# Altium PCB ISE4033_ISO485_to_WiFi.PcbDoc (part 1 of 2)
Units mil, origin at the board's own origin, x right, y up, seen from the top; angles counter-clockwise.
Board outline 4100 x 3450 mil, 4 copper layers (Top Layer, Signal Layer 1, Signal Layer 2, Bottom Layer), stack 52.6 mil thick; 125 components, 68 nets, 339 pads, 551 vias.
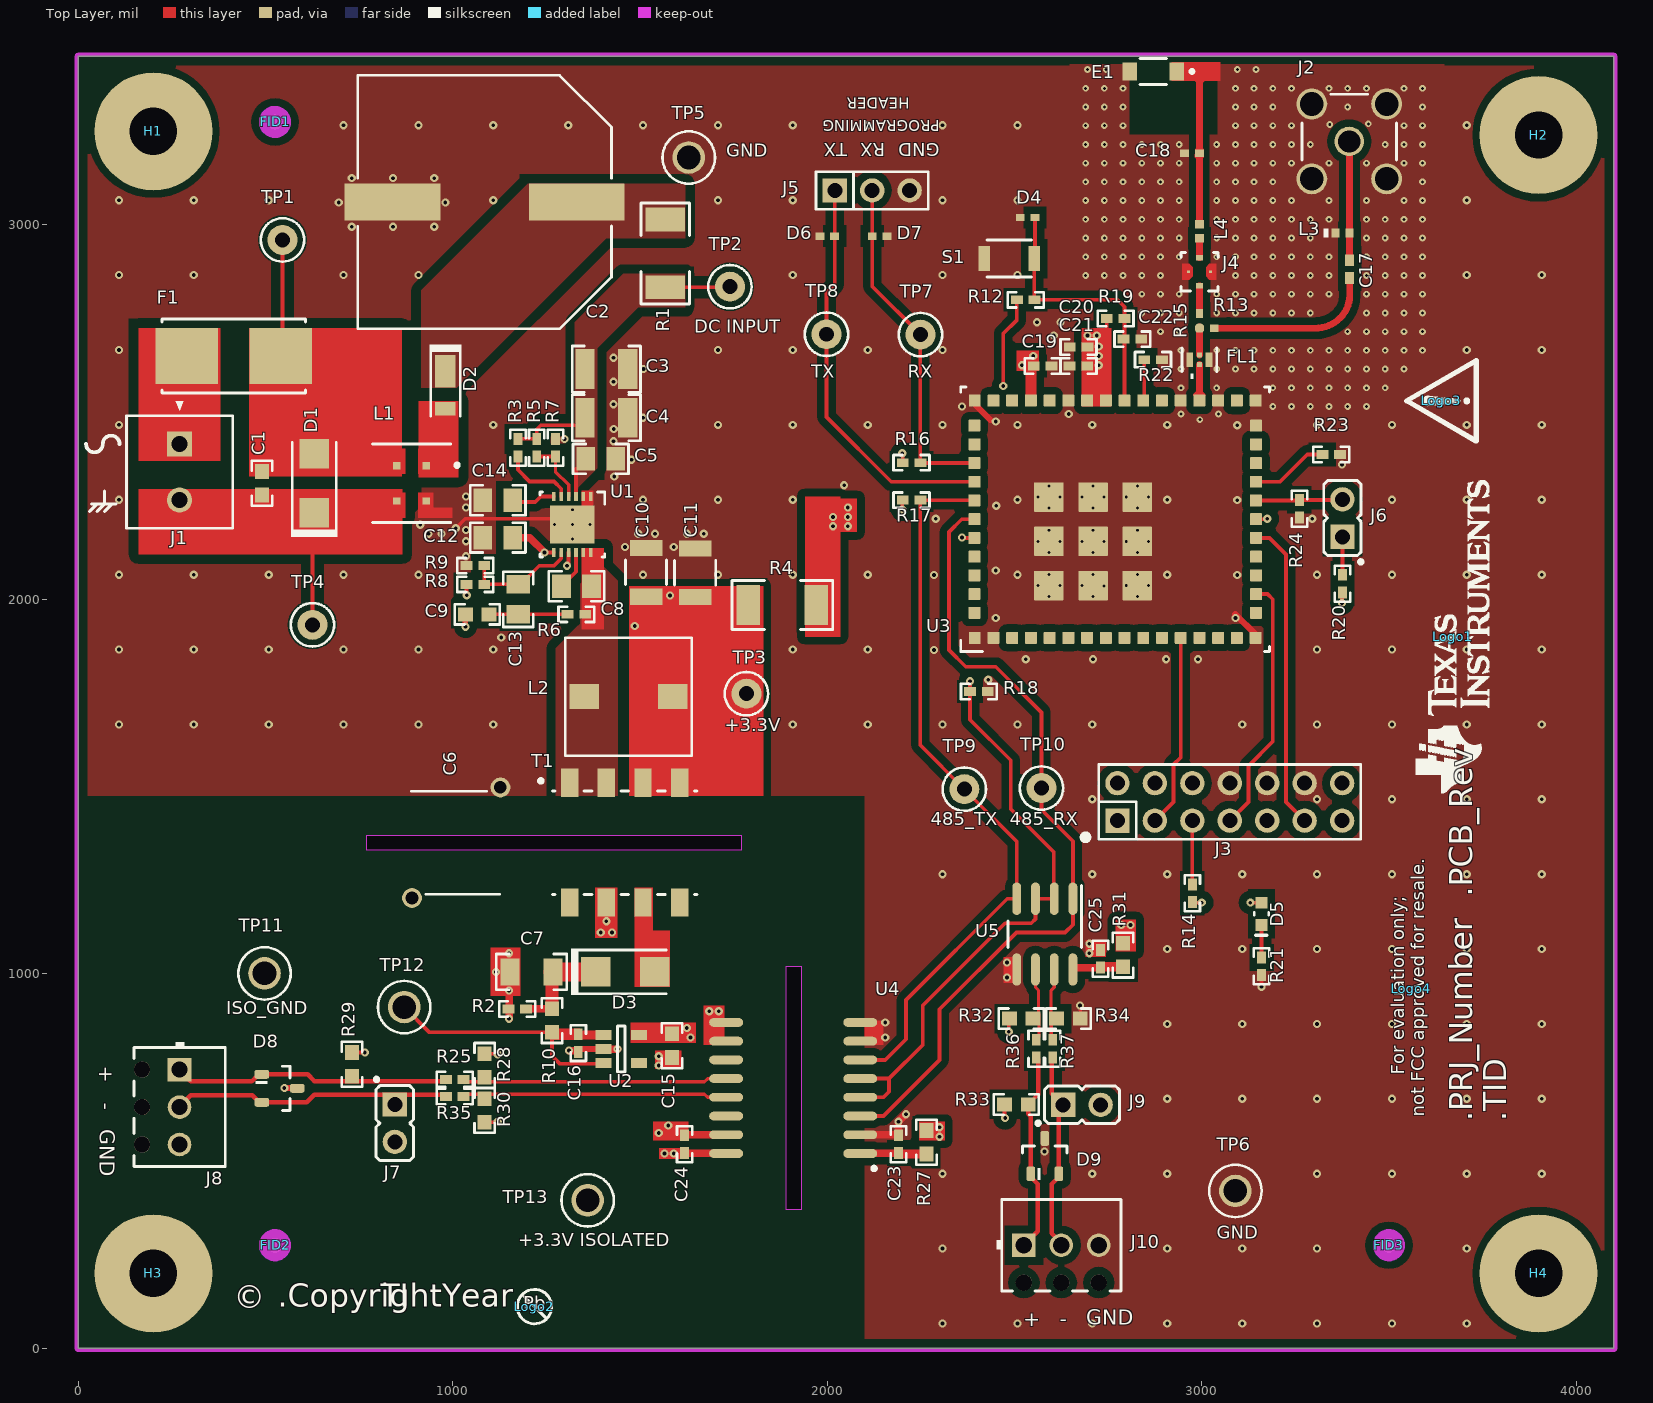
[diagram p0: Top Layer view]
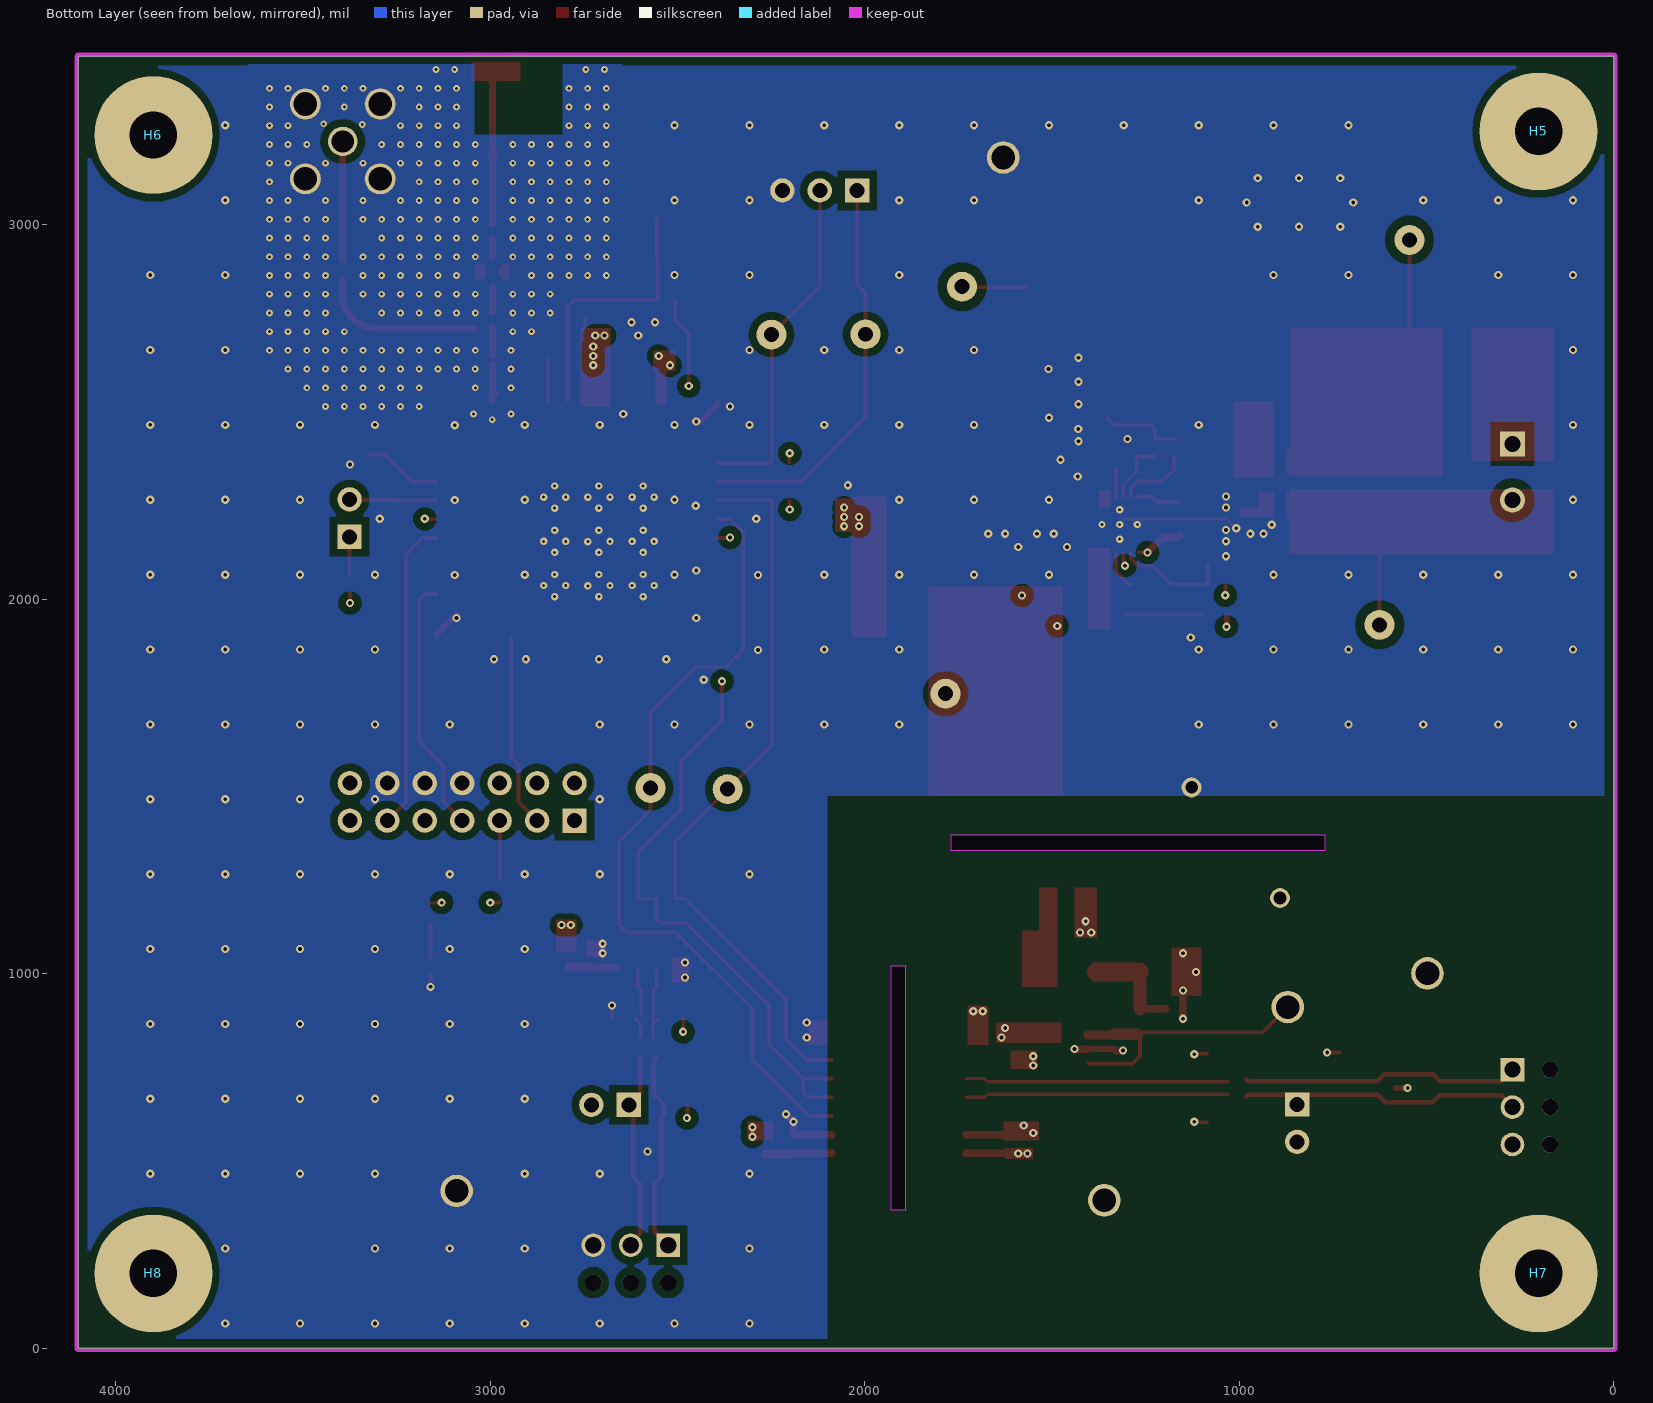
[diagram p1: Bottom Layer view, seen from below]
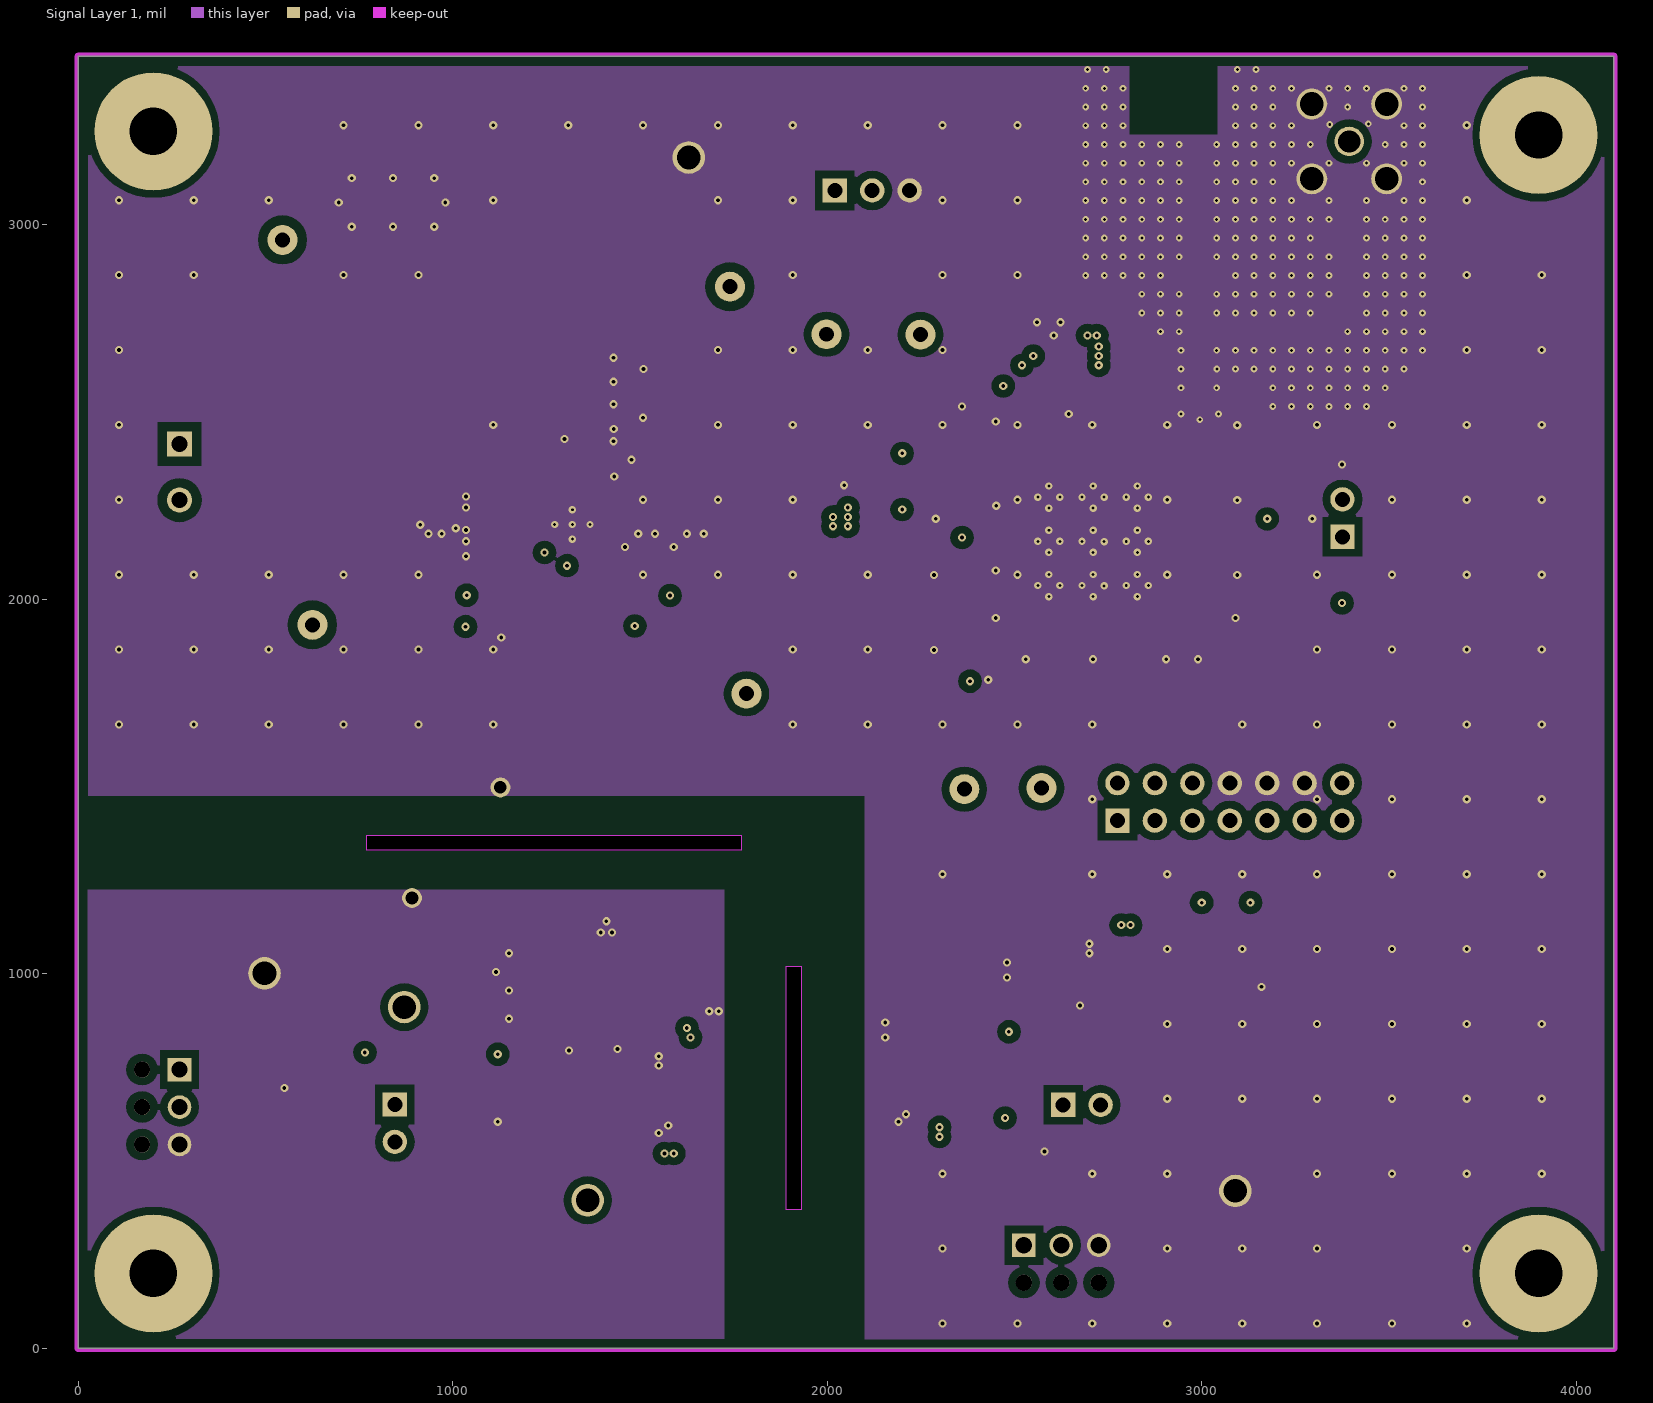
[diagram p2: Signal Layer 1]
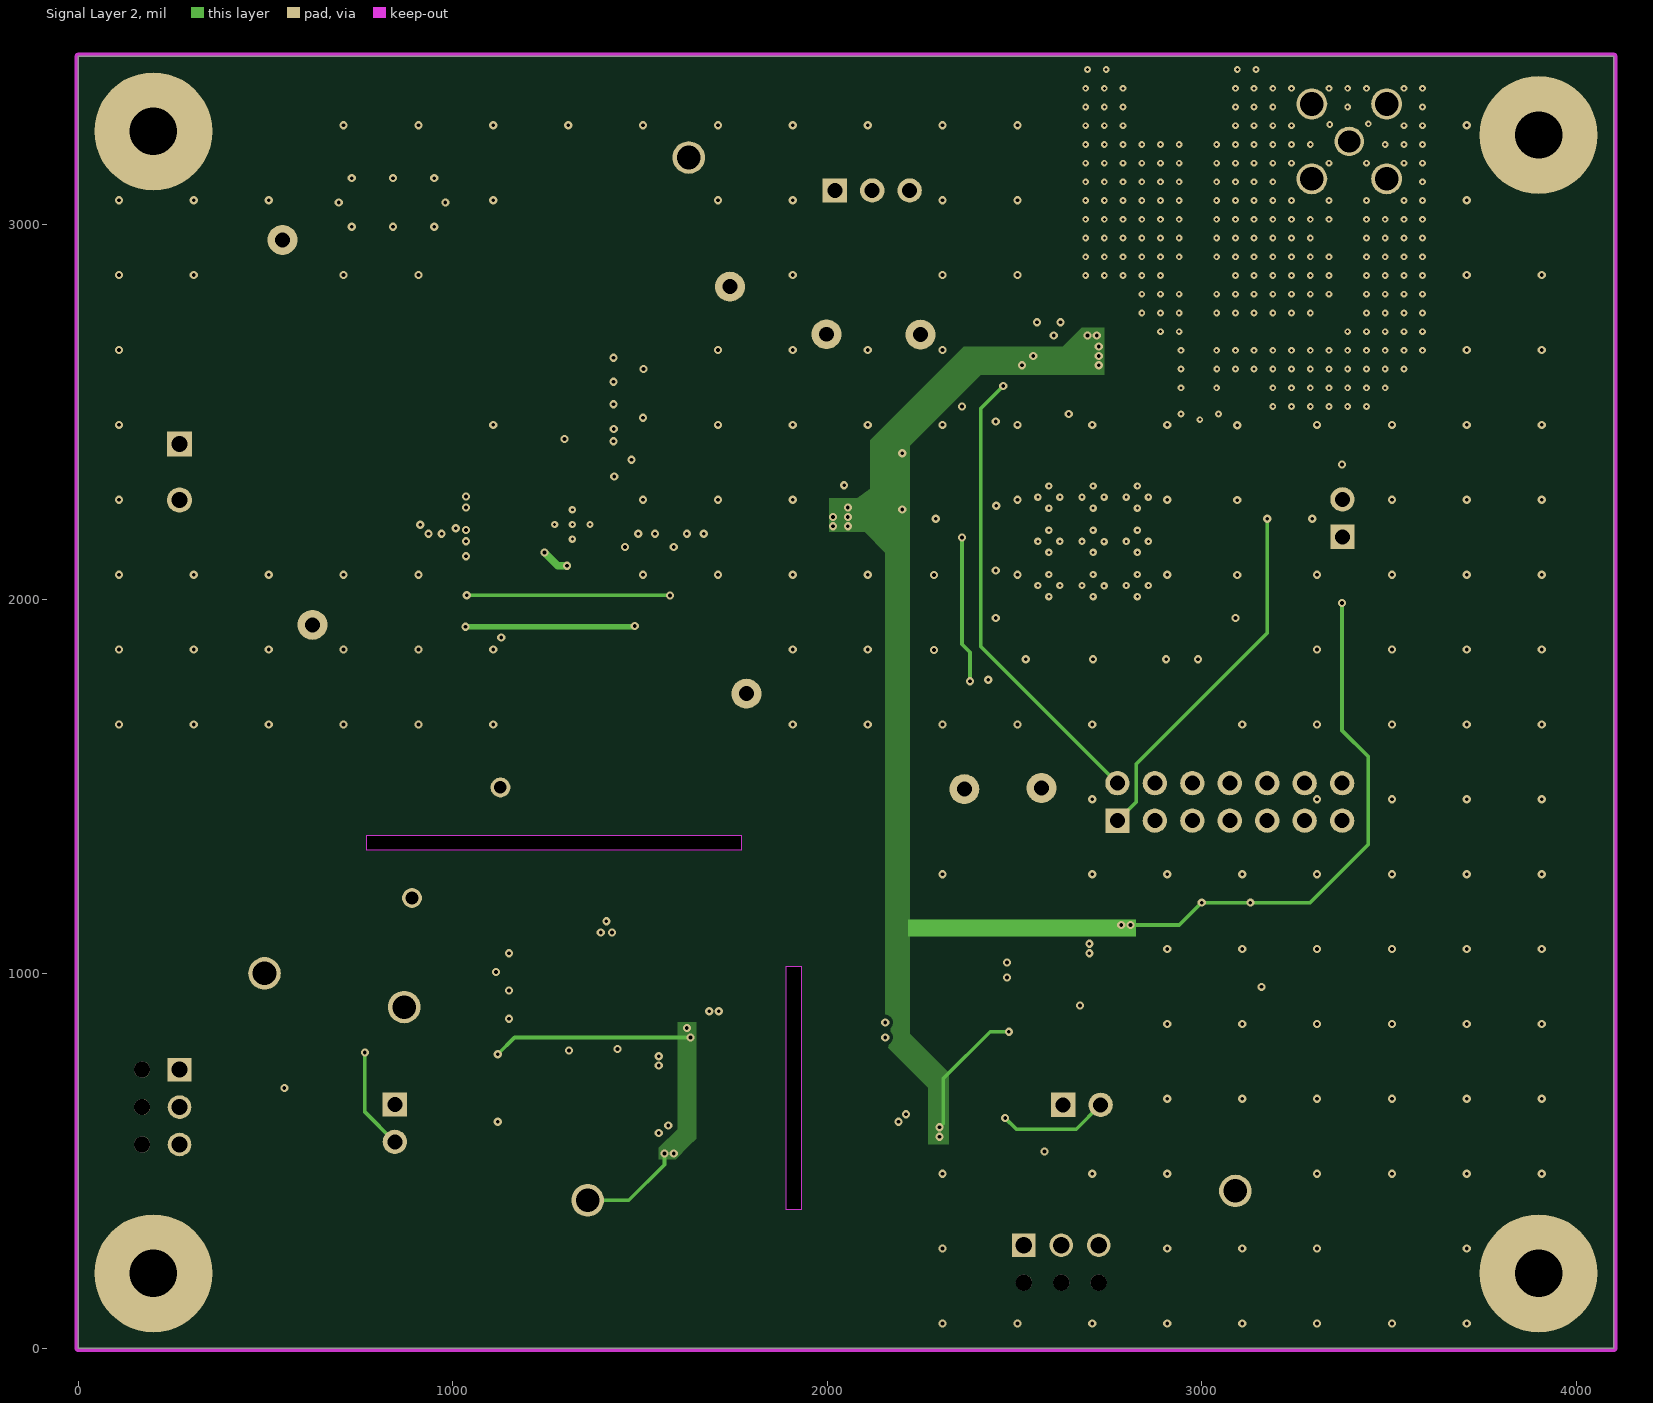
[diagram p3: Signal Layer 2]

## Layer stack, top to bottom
Top Solder: solder mask 0.4, Solder Resist, Dk 3.5
Top Layer: signal copper 1.4
Dielectric1: core 10, FR-4 High TG, Dk 4.2
Signal Layer 1: signal copper 1.4
Dielectric 2: prepreg 27, FR-4 High TG, Dk 4.2
Signal Layer 2: signal copper 1.4
Dielectric 3: core 10, FR-4 High TG, Dk 4.2
Bottom Layer: signal copper 1.4
Bottom Solder: solder mask 0.4, Solder Resist, Dk 3.5

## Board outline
0,0 4100,0 4100,3450 0,3450
cut-out: 1930,1020 1930,370 1890,370 1890,1020
cut-out: 770,1370 1770,1370 1770,1330 770,1330

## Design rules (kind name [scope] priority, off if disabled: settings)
AcuteAngle [All] p1: minimum=4.50000000000000E+0001 checktracksonly=FALSE
AssemblyTestPointUsage [All] p1: valid=2
Clearance "Clearance_special nets" [innet('IN1') or  innet('IN2') or    innet('IN1_F') or    innet('IN1_FL') or    innet('VIN_FLT') or    innet('PS_VIN') or    innet('BST') or    innet('SW') vs inpoly] p1: gap=25
Clearance "Clearance_GND poly" [(innet('GND') or innet('ISO_GND')) and inpoly] p2: gap=20
Clearance Clearance_Keepouts [((IsTrack Or IsArc) And Not InPoly) And IsFree and IsKeepOut vs ((IsTrack Or IsArc) And Not InPoly) And IsFree and IsKeepOut] p3: gap=0
Clearance Clearance_BoardEdge_MountingHoles [OnCopper and InComponentClass('Mounting Holes') vs IsKeepOut] p4: gap=40
Clearance Clearance_BoardEdge_Poly [OnCopper and InPoly vs IsKeepOut] p5: gap=25
Clearance Clearance_BoardEdge [OnCopper and Not InComponentClass('Logo') and not InComponentClass('FiducialMark') and not InRegion(1000,500,4000,800) and Not IsKeepout vs IsKeepOut] p6: gap=15
Clearance Clearance_Poly [InPolygon] p7: gap=10
Clearance [All] p8: gap=7.6
ComponentClearance ComponentClearance_1 [InComponent('R13') vs InComponent('R15')] p1: gap=0 collisioncheckmode=3 verticalgap=0 showdistances=FALSE
ComponentClearance ComponentClearance_MountingHoles_FiducialMarks [InComponentClass('Mounting Holes') vs InComponentClass('FiducialMark')] p2: gap=50 collisioncheckmode=3 verticalgap=10 showdistances=FALSE
ComponentClearance ComponentClearance_Shunt [InComponentClass('Header') vs InComponentClass('Shunt')] p3: gap=0 collisioncheckmode=3 verticalgap=0 showdistances=FALSE
ComponentClearance ComponentClearance_Logo [InComponentClass('Logo')] p4: gap=50 collisioncheckmode=3 verticalgap=10 showdistances=FALSE
ComponentClearance ComponentClearance_ScrewToNut [(HasFootprint('NY PMS 440 0025 PH')) vs (HasFootprint('Keystone_1902C'))] p5: gap=5 collisioncheckmode=3 verticalgap=10 showdistances=FALSE
ComponentClearance ComponentClearance_MountingHoles [InComponentClass('Mounting Holes')] p6: gap=100 collisioncheckmode=3 verticalgap=100000 showdistances=FALSE
ComponentClearance ComponentClearance_SmallPassives [HasFootprint('0201*') or HasFootprint('0402*') or HasFootprint('0508') or HasFootprint('0603*') or HasFootprint('0612') or HasFootprint('0805*') or HasFootprint('0815*') or HasFootprint('0830*') or HasFootprint('1206*') or HasFootprint('1210*') or HasFootprint('1808*') or HasFootprint('1812*') or HasFootprint('1825*') or HasFootprint('2010*') or HasFootprint('2220*') or HasFootprint('2225*') or HasFootprint('2512*') or HasFootprint('2728*') or HasFootprint('3518*') vs HasFootprint('0201*') or HasFootprint('0402*') or HasFootprint('0508') or HasFootprint('0603*') or HasFootprint('0612') or HasFootprint('0805*') or HasFootprint('0815*') or HasFootprint('0830*') or HasFootprint('1206*') or HasFootprint('1210*') or HasFootprint('1808*') or HasFootprint('1812*') or HasFootprint('1825*') or HasFootprint('2010*') or HasFootprint('2220*') or HasFootprint('2225*') or HasFootprint('2512*') or HasFootprint('2728*') or HasFootprint('3518*')] p7: gap=20 collisioncheckmode=3 verticalgap=10 showdistances=FALSE
ComponentClearance ComponentClearance_THtoSMT [IsThruComponent vs IsSMTComponent] p8: gap=25 collisioncheckmode=3 verticalgap=30 showdistances=FALSE
ComponentClearance ComponentClearance_THtoTH [IsThruComponent vs IsThruComponent] p9: gap=100 collisioncheckmode=3 verticalgap=30 showdistances=FALSE
ComponentClearance [All] p10: gap=40 collisioncheckmode=3 verticalgap=10 showdistances=FALSE
DiffPairsRouting DiffPairsRouting-140 [InDifferentialPair('ISO485') or  InDifferentialPair('RS485')] p1: maxlimit=70 minlimit=25 mostfreqgap=25 toplayer_minwidth=8.5 toplayer_maxwidth=8.5 toplayer_prefwidth=8.5 midlayer1_minwidth=8.5 midlayer1_maxwidth=8.5 midlayer1_prefwidth=8.5 midlayer2_minwidth=8.5 midlayer2_maxwidth=8.5 midlayer2_prefwidth=8.5 bottomlayer_minwidth=8.5 bottomlayer_maxwidth=8.5 bottomlayer_prefwidth=8.5 maxuncoupledlength=500
DiffPairsRouting DiffPairsRouting-120 [InDifferentialPair('ISO485_OUT') or  InDifferentialPair('RS485_OUT')] p2: maxlimit=70 minlimit=25 mostfreqgap=25 toplayer_minwidth=12 toplayer_maxwidth=12 toplayer_prefwidth=12 midlayer1_minwidth=12 midlayer1_maxwidth=12 midlayer1_prefwidth=12 midlayer2_minwidth=12 midlayer2_maxwidth=12 midlayer2_prefwidth=12 bottomlayer_minwidth=12 bottomlayer_maxwidth=12 bottomlayer_prefwidth=12 maxuncoupledlength=1000
FabricationTestPointUsage TestPointUsage [All] p1: valid=2 allowmultiple=FALSE
FabricationTestpoint Testpoint [All] p1: side=3 testpointundercomponent=TRUE minsize=40 maxsize=100 preferedsize=60 minholesize=0 maxholesize=40 preferedholesize=32 testpointgrid=1 allowsidetop=TRUE allowsidebottom=TRUE usegrid=TRUE gridtolerance=0.01
FanoutControl Fanout_LCC [IsLCC] p1: bgadir=Out bgaviamode=Centered fanoutstyle=Auto fanoutdirection=Alternating viagrid=1 // Fanout_LCC (Default Rule)
FanoutControl Fanout_BGA [IsBGA] p2: bgadir=Out bgaviamode=Centered fanoutstyle=Auto fanoutdirection=Alternating viagrid=1 // Fanout_BGA (Default Rule)
FanoutControl Fanout_Default [All] p4: bgadir=Out bgaviamode=Centered fanoutstyle=Auto fanoutdirection=Alternating viagrid=1 // Fanout_Default (Default Rule)
FanoutControl Fanout_Small [(CompPinCount < 5)] p5: bgadir=Out bgaviamode=Centered fanoutstyle=Auto fanoutdirection=OutThenIn viagrid=1 // Fanout_Small (Default Rule)
HoleSize [All] p1: absolutevalues=TRUE maxlimit=251 minlimit=7.8 maxpercent=80.000 minpercent=20.000
MinimumAnnularRing MinimumAnnularRing_ThermalPadVias [IsVia and InAnyComponent] p1: minimumring=5.91
MinimumAnnularRing [All] p2: minimumring=5
MinimumSolderMaskSliver MinimumSolderMaskSliver_Logo [InComponentClass('Logo') vs InComponentClass('Logo')] p1: minsoldermaskwidth=0.7
MinimumSolderMaskSliver [All] p2: minsoldermaskwidth=3.94
PlaneConnect [All] p1: planeconnectstyle=Relief reliefexpansion=10 reliefentries=4 reliefconductorwidth=10 reliefairgap=10
PolygonConnect [All] p1: connectstyle=Direct reliefconductorwidth=10 reliefentries=4 polygonreliefangle="90 Angle" airgapwidth=10
RoutingVias ThermalPadVias [IsVia and InAnyComponent] p1: holewidth=7.87 width=19.68 viastyle="Through Hole" minholewidth=7.87 minwidth=19.68 maxholewidth=12.99 maxwidth=23.62
RoutingVias [All] p2: holewidth=10 width=22 viastyle="Through Hole" minholewidth=7.87 minwidth=18 maxholewidth=40 maxwidth=65
SilkToBoardRegionClearance [Not ((IsComment or IsDesignator) And (Hide <> 'False')) and not InRegion(1000,500,4000,800)] p1:
SilkToSilkClearance SilkToSilkClearance_Pb-FreeLogo [(HasFootprint('Pb-Free_Overlay_Medium') OR HasFootprint('Pb-Free_Overlay_Small')) vs (HasFootprint('Pb-Free_Overlay_Medium') OR HasFootprint('Pb-Free_Overlay_Small'))] p1: silktosilkclearance=0
SilkToSilkClearance [All] p2: silktosilkclearance=3
SilkToSolderMaskClearance "Silk to Solder Mask Opening" [All] p1: minsilkscreentomaskgap=1 clearancetoexposedcopper=FALSE
SolderMaskExpansion [All] p1: expansion=1.97
UnpouredPolygon [All] p1: allowunpoured=FALSE
Width Width_50OHM [InNetClass('50 OHM')] p1: maxlimit=20 minlimit=18 preferedwidth=18
Width [All] p2: maxlimit=100 minlimit=8 preferedwidth=10 checkconnectedcopper=TRUE
14 further rules are at their usual default settings.

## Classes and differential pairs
component class ISE4037_RS485_to_WiFi_Sheet4: C23 C24 C25 D8 D9 J7 J8 J9 J10 R25 R27 R28 R29 R30 R31 R32 R33 R34 R35 R36 R37 SH-J7 SH-J9 SH-J10 SH-J11 U4 U5
component class AssemblyNote: ZZ1 ZZ2 ZZ3 ZZ4
component class FiducialMark: FID1 FID2 FID3
component class ISE4037_RS485_to_WiFi_Sheet5: FID1 FID2 FID3 H1 H2 H3 H4 H5 H6 H7 H8 Logo1 Logo2 Logo3 Logo4 ZZ1 ZZ2 ZZ3 ZZ4
component class Logo: Logo1
component class "Mounting Holes": H1 H2 H3 H4
component class Header: J3 J5 J6 J7 J9
component class ISE4037_RS485_to_WiFi_Sheet2: C1 C2 C3 C4 C5 C6 C7 C8 C9 C10 C11 C12 C13 C14 C15 C16 D1 D2 D3 D5 F1 J1 L1 L2 R1 R2 R3 R4 R5 R6 R7 R8 R9 R10 R21 T1 TP1 TP2 TP3 TP4 TP5 TP6 TP11 TP12 TP13 U1 U2
component class ISE4037_RS485_to_WiFi_Sheet3: C17 C18 C19 C20 C21 C22 D4 D6 D7 E1 FL1 J2 J3 J4 J5 J6 L3 L4 R12 R13 R14 R15 R16 R17 R18 R19 R20 R22 R23 R24 S1 TP7 TP8 TP9 TP10 U3
net class "50 OHM": ANT_LEG CC_RF_OUT J4-2 RF_FL_O SMA_LEG SMA_OUT
differential pair RS485: +RS485_P -RS485_N
differential pair RS485_OUT: +RS485_OUT_P -RS485_OUT_N
differential pair ISO485: +ISO485_P -ISO485_N
differential pair ISO485_OUT: +ISO485_OUT_P -ISO485_OUT_N

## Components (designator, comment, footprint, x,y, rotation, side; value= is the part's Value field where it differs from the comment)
C1 "06031C102KAT2A" 0603 490,2310 r270 top
C2 "EEV-FK1K331M" SM_RADIAL_J16 1085,3061 r180 top
C3 "C1210C225K1RACTU" 1210 1410,2615 r0 top
C4 "C1210C225K1RACTU" 1210 1410,2485 r0 top
C5 "C0805C104K1RACTU" 0805_HV 1395,2375 r0 top
C6 "DEBE33F102ZC3B" CAPRD750W60D700H1000 1009,1350 r90 top
C7 "C3216X7R1C475K" 1206 1210,1005 r180 top
C8 "08051C223KAT2A" 0805_HV 1330,2035 r180 top
C9 "06031C472KAT2A" 0603 1065,1960 r0 top
C10 "C1210C107M8PACTU" 1210_280 1516,2072 r90 top
C11 "C1210C107M8PACTU" 1210_280 1647,2071 r90 top
C12 "C0805C104K1RACTU" 0805_HV 1120,2165 r180 top
C13 "C0805C104K1RACTU" 0805_HV 1175,2000 r90 top
C14 "C0805C823K1RACTU" 0805_HV 1120,2265 r180 top
C15 "GRM188R71A105KA61D" 0603 1585,808 r270 top
C16 "GRM155R71A104KA01D" 0402 1335,815 r270 top
C17 "GRM1555C1H100JA01D" 0402 3395,2882 r270 top
C18 "GRM1555C1H1R0BA01D" 0402L#1 2974,3191 r180 top
C19 "GRM155R60J475ME87D" 0402 2575,2623 r0 top
C20 "GRM155R71A104KA01D" 0402 2671,2674 r180 top
C21 "GRM155R60J475ME87D" 0402 2670.92,2623.03 r180 top
C22 "GRM155R71A104KA01D" 0402 2815,2695 r0 top
C23 "GRM155R71A104KA01D" 0402 2190,545 r270 top
C24 "GRM155R71A104KA01D" 0402 1619,545 r270 top
C25 "GRM155R71A104KA01D" 0402 2730,1040 r270 top
D1 "SMAJ51CA" SMA 630,2310 r90 top
D2 "DFLS1200-7" powerDI123 980,2559 r270 top
D3 "CD214A-B1100LF" SMA 1460,1005 r0 top
D4 "TPD1E10B06DPYR" DPY0002A 2535,3020 r180 top
D5 "LG L29K-G2J1-24-Z" "LG L29K_GREEN" 3160,1160 r270 top
D6 "TPD1E10B06DPYR" DPY0002A 2000,2970 r180 top
D7 "TPD1E10B06DPYR" DPY0002A 2140,2970 r0 top
D8 "SM712.TCT" SOT-23 537,694 r0 top
D9 "SM712.TCT" SOT-23 2581,513 r90 top
E1 "AH316M245001-T" TAYO_AH316M 2870.5,3410 r180 top locked
F1 "0154002.DRT" FUSE_154 415,2650 r180 top
FID1 "Fiducial" Fiducial10-20 525,3275 r0 top
FID2 "Fiducial" Fiducial10-20 525,275 r0 top
FID3 "Fiducial" Fiducial10-20 3500,275 r0 top
FL1 "DEA202450BT-1294C1-H" TDK_DEA202450BT-1294C1-H 2994,2640 r180 top
H1 "NY PMS 440 0025 PH" "NY PMS 440 0025 PH" 200,3250 r0 top locked
H2 "NY PMS 440 0025 PH" "NY PMS 440 0025 PH" 3900,3240 r0 top locked
H3 "NY PMS 440 0025 PH" "NY PMS 440 0025 PH" 200,200 r0 top locked
H4 "NY PMS 440 0025 PH" "NY PMS 440 0025 PH" 3900,200 r0 top locked
H5 "1902C" Keystone_1902C 200,3250 r180 bottom locked
H6 "1902C" Keystone_1902C 3900,3240 r180 bottom locked
H7 "1902C" Keystone_1902C 200,200 r180 bottom locked
H8 "1902C" Keystone_1902C 3900,200 r180 bottom locked
J1 "1727010" PhoenixConact_1727010 270,2340 r270 top
J2 "5-1814832-1" TE_5-1814832-1 3394,3223 r90 top
J3 "PEC07DAAN" CONN_PEC07DAAN 3075,1459 r0 top
J4 "MM8030-2610RJ3" MuRata_MM8030-2610 2994,2875 r90 top
J5 "PBC03SAAN" PBC03SAAN 2120,3092 r0 top
J6 "PBC02SAAN" Sullins_PBC02SAAN 3375.92,2217.03 r180 top
J7 "PBC02SAAN" Sullins_PBC02SAAN 845,601 r0 top
J8 "1725669" Phoenix_1725669 270,644 r270 top
J9 "PBC02SAAN" Sullins_PBC02SAAN 2680,650 r90 top
J10 "1725669" Phoenix_1725669 2625,275 r0 top
L1 "DLW5BTM102TQ2K" DLW5BT_TQ2 890,2310 r270 top
L2 "7447789147" WE-PD-S 1469,1740 r0 top
L3 "LQG15HS3N6S02D" IND_LQG15H 3376,2978 r0 top
L4 "LQP15MN3N6B02D" LQP_0402 2994,2983 r90 top
Logo1 "Texas Instruments" TI_Stacked_Overlay_Small 3670,1900 r90 top
Logo2 "Pb-Free Symbol" Pb-Free_Overlay_Small 1218,111 r0 top
Logo3 "CAUTION.  READ USER GUIDE BEFORE USE" IEC_Caution_Small 3640,2530 r90 top
Logo4 "FCC disclaimer" FCC_disclaimer_stacked 3560,960 r90 top
R1 "CRCW20100000Z0EF" 2010 1567,2924 r270 top
R2 "CRCW04022K00FKED" 0402 1172,906 r0 top
R3 "CRCW0402110KFKED" 0402 1174,2405 r270 top
R4 "CRCW20100000Z0EF" 2010 1880,1985 r0 top
R5 "CRCW0402127KFKED" 0402 1224,2405 r90 top
R6 "CRCW0402100KFKED" 0402 1330,1960 r180 top
R7 "CRCW040217K8FKED" 0402 1274,2405 r270 top
R8 "CRCW04021K96FKED" 0402 1060,2040 r180 top
R9 "CRCW04023K01FKED" 0402 1060,2090 r0 top
R10 "CRCW06030000Z0EA" 0603 1265,875 r270 top
R12 "CRCW04020000Z0ED" 0402 2530,2800 r180 top
R13 "CRCW04020000Z0ED" 0402L#2 3014,2724 r0 top
R14 "CRCW04020000Z0ED" 0402 2975,1215 r270 top
R15 "CRCW04020000Z0ED" 0402L#3 2994,2744 r270 top
R16 "CRCW0402100KFKED" 0402 2225,2365 r180 top
R17 "CRCW0402100KFKED" 0402 2225,2265 r180 top
R18 "CRCW04022K67FKED" 0402 2405,1754 r180 top
R19 "CRCW0402100KFKED" 0402 2770,2750 r180 top
R20 "CRCW0402270RJNED" 0402 3375.92,2042.03 r270 top
R21 "CRCW0402402RFKED" 0402 3160,1020 r90 top
R22 "CRCW0402100KFKED" 0402 2870,2640 r180 top
R23 "CRCW0402100KFKED" 0402 3345.92,2387.03 r180 top
R24 "CRCW04022K67FKED" 0402 3260.92,2242.03 r90 top
R25 "CRCW040210R0FKED" 0402 1005,718 r180 top
R27 "CRCW06030000Z0EA" 0603 2265,550 r90 top
R28 "CRCW0603348RFKEA" 0603 1085,755 r90 top
R29 "RC0603FR-07120RL" 0603 731,758 r90 top
R30 "CRCW0603348RFKEA" 0603 1085,635 r90 top
R31 "CRCW06030000Z0EA" 0603 2790,1050 r90 top
R32 "CRCW0603348RFKEA" 0603 2518,880 r180 top
R33 "RC0603FR-07120RL" 0603 2505,651 r180 top
R34 "CRCW0603348RFKEA" 0603 2644,880 r180 top
R35 "CRCW040210R0FKED" 0402 1005,672 r180 top
R36 "CRCW040210R0FKED" 0402 2558,800 r270 top
R37 "CRCW040210R0FKED" 0402 2602,800 r270 top
S1 "B3U-1000P" SW_B3U-1000P 2485.92,2910.03 r180 top
T1 "750315547" Wurth_750315547_48 1459,1350 r0 top
TP1 "5002" Keystone5002 545,2960 r0 top
TP2 "5000" Keystone5000 1740,2835 r0 top
TP3 "5000" Keystone5000 1784,1748 r0 top
TP4 "5002" Keystone5002 625,1932 r0 top
TP5 "5128" Keystone5128 1630,3180 r0 top
TP6 "5128" Keystone5128 3090,420 r0 top
TP7 "5003" Keystone5003 2249,2707 r0 top
TP8 "5004" Keystone5004 1998,2708 r0 top
TP9 "5003" Keystone5003 2366,1493 r0 top
TP10 "5004" Keystone5004 2572,1496 r0 top
TP11 "5126" Keystone5126 497,1001 r0 top
TP12 "5129" Keystone5129 870,911 r0 top
TP13 "5125" Keystone5125 1360,395 r0 top
U1 "LM5160DNTR" DNT0012B 1319,2200 r270 top
U2 "TLV71333PDBV" DBV0005A_N 1449.84,799 r0 top
U3 "CC3200MODR1M2AMOBR" MOB0063A 2768.92,2214.03 r90 top
U4 "ISO15DW" DW0016A_N 1909,695 r180 top
U5 "SN65HVD72DR" D0008A_N 2581,1106 r270 top
ZZ1 "These assemblies are ESD sensitive, ESD precautions shall be observed." AssemblyNote 185,3829.11 r0 top
ZZ2 "These assemblies must be clean and free from flux and all contaminants. Use of no clean flux is not acceptable." AssemblyNote 185,3740.56 r0 top
ZZ3 "These assemblies must comply with workmanship standards IPC-A-610 Class 2, unless otherwise specified." AssemblyNote 185,3652 r0 top
ZZ4 "Place SH-J6 on J6, SH-J7 on J7, and SH-J9 on J9" AssemblyNote 185,3570 r0 top

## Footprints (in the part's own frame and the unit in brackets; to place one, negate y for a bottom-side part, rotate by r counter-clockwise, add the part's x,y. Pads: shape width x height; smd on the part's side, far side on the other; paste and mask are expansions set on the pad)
0402 [mm] "0402 from SM-752 data"
  rect 0.8x0.6 smd: 1(-0.6,0) 2(0.6,0)
  silkscreen extent -1.22,-0.52 1.22,0.52, body extent -0.55,-0.3 0.55,0.3, height 0.6
0402L#1 [mm] "0402 from SM-752 data"
  rect 0.6x0.5 smd: 1(-0.5,0) 2(0.5,0)
  body extent -0.55,-0.3 0.55,0.3, height 0.6
0402L#2 [mm] "0402 from SM-752 data"
  rrect50% 0.6x0.5 smd: 1(-0.5,0)
  rect 0.6x0.5 smd: 2(0.5,0)
  body extent -0.55,-0.3 0.55,0.3, height 0.6
0402L#3 [mm] "0402 from SM-752 data"
  rect 0.6x0.5 smd: 1(-0.5,0)
  rrect50% 0.6x0.5 smd: 2(0.5,0)
  body extent -0.55,-0.3 0.55,0.3, height 0.6
0603 [mm] "0603 from SM-752 data"
  rect 1x0.95 smd: 1(-0.8,0) 2(0.8,0)
  silkscreen extent -1.52,-0.69 1.52,0.69, body extent -0.87,-0.47 0.87,0.47, height 0.85
0805_HV [mil] "0805 with 30mil clearance between pads"
  rect 50x63 smd: 1(-40,0) 2(40,0)
  silkscreen extent -74,-40 74,40, body extent -43,-29 43,29, height 43
1206 [mm] "1206 from SM-752 data"
  rect 1.3x1.85 smd: 1(-1.45,0) 2(1.45,0)
  silkscreen extent -2.4,-1.21 2.4,1.21, body extent -1.7,-0.9 1.7,0.9, height 1.35
1210 [mm] "1210 from SM-752 data"
  rect 1.3x2.7 smd: 1(-1.45,0) 2(1.45,0)
  silkscreen extent -2.32,-1.57 2.32,1.57, body extent -1.7,-1.35 1.7,1.35, height 1.35
1210_280 [mm] "SMD, 2-Leads, Body 3.6x2.8mm, Height 2.8mm"
  rect 1.1x2.2 smd: 1(-1.65,0) 2(1.65,0)
  silkscreen extent -0.84,-1.4 0.84,1.4, body extent -1.8,-1.4 1.8,1.4, height 2.8
2010 [mm] "Chip Capacitor, Body 5.08x2.54mm, IPC Medium Density"
  rect 1.6x2.7 smd: 1(-2.3,0) 2(2.3,0)
  silkscreen extent -3.42,-1.65 3.42,1.65, body extent -2.73,-1.45 2.73,1.45, height 1.66
AssemblyNote [mil] "Assembly Note"
CAPRD750W60D700H1000 [mm] "muRata"
  round 1.35 hole 0.85: 1(-3.75,3) 2(3.75,-3)
  silkscreen extent -3.5,-2.95 3.47,3.05, body extent -4.26,-3.51 4.26,3.51, height 9.97
CONN_PEC07DAAN [mm] "SULLINS"
  rect 1.65x1.65 hole 1.016 mask+0: 1(-7.62,-1.27)
  round 1.65 hole 1.016 mask+0: 2(-7.62,1.27) 3(-5.08,-1.27) 4(-5.08,1.27) 5(-2.54,-1.27) 6(-2.54,1.27) 7(0,-1.27) 8(0,1.27) 9(2.54,-1.27) 10(2.54,1.27) 11(5.08,-1.27) 12(5.08,1.27) 13(7.62,-1.27) 14(7.62,1.27)
  silkscreen extent -9.99,-2.6 8.89,2.54, body extent -8.95,-2.6 8.95,2.6, height 11.43
D0008A_N [mm] "SOIC, 8-Leads, Body 4.9x3.9mm, Pitch 1.27mm, IPC Medium Density"
  oval 2.2x0.6 smd: 1(-2.4,1.905) 2(-2.4,0.635) 3(-2.4,-0.635) 4(-2.4,-1.905) 5(2.4,-1.905) 6(2.4,-0.635) 7(2.4,0.635) 8(2.4,1.905)
  silkscreen extent -3.3,-2.5 0.9,2.5, body extent -3,-2.45 3,2.45, height 1.63
DBV0005A_N [mm] "SOT23, 5-Leads, Body 2.9x1.6mm, Pitch 0.95mm, Lead Span 2.8mm, IPC Medium Density"
  rect 1.1x0.65 smd: 1(-1.2,0.95) 2(-1.2,0) 3(-1.2,-0.95) 4(1.2,-0.95) 5(1.2,0.95)
  silkscreen extent -0.25,-1.55 0.25,1.55, body extent -1.42,-1.46 1.42,1.46, height 1.08
DLW5BT_TQ2 [mm] "SMD, 4-Leads, Body 5x5mm"
  rect 0.5x0.5 smd: 1(-1.2,1) 2(-1.2,-1) 3(1.2,-1) 4(1.2,1)
  Top Layer region: -2.35,-0.45 -0.65,-0.45 -0.65,-1.45 -1.65,-1.45 -1.65,-2.75 -2.35,-2.75
  Top Layer region: -2.35,0.45 -0.65,0.45 -0.65,1.45 -1.65,1.45 -1.65,2.75 -2.35,2.75
  Top Layer region: 2.35,-0.45 0.65,-0.45 0.65,-1.45 1.65,-1.45 1.65,-2.75 2.35,-2.75
  Top Layer region: 2.35,0.45 0.65,0.45 0.65,1.45 1.65,1.45 1.65,2.75 2.35,2.75
  silkscreen extent -2.65,-2.65 2.65,3.2, body extent -2.65,-2.65 2.65,2.65, height 2.51
DNT0012B [mm] "SON, 12-Leads, Body 4x4mm, Pitch 0.5mm"
  rect 0.6x0.25 smd: 1(-1.9,1.25) 2(-1.9,0.75) 3(-1.9,0.25) 4(-1.9,-0.25) 5(-1.9,-0.75) 6(-1.9,-1.25) 7(1.9,-1.25) 8(1.9,-0.75) 9(1.9,-0.25) 10(1.9,0.25) 11(1.9,0.75) 12(1.9,1.25)
  rect 2.6x3 smd paste-1.3: 13(0,0)
  silkscreen extent -2.2,-2.2 2.2,2.2, body extent -2.05,-2.05 2.05,2.05, height 0.81
DPY0002A [mm] "R-PX2SON-N2"
  rect 0.6x0.5 smd: 1(-0.5,0) 2(0.5,0)
  body extent -0.55,-0.35 0.55,0.35, height 0.4
DW0016A_N [mm] "SOIC, 16-Leads, Body 10.3x7.5mm, Pitch 1.27mm, IPC Medium Density"
  oval 2.3x0.6 smd: 1(-4.55,4.445) 2(-4.55,3.175) 3(-4.55,1.905) 4(-4.55,0.635) 5(-4.55,-0.635) 6(-4.55,-1.905) 7(-4.55,-3.175) 8(-4.55,-4.445) 9(4.55,-4.445) 10(4.55,-3.175) 11(4.55,-1.905) 12(4.55,-0.635) 13(4.55,0.635) 14(4.55,1.905) 15(4.55,3.175) 16(4.55,4.445)
  body extent -5.14,-5.13 5.14,5.13, height 2.5
FCC_disclaimer_stacked [mil]
Fiducial10-20 [mm]
  round 1 smd mask+0.5: 1(0,0)
  Top Layer keep-out circle w1.178: c0,0 r0.5
FUSE_154 [mm] "SMD, 2-Leads, Body 9.73x5.03mm"
  rect 4.245x3.81 smd: 1(-3.187,0) 2(3.187,0)
  silkscreen extent -4.86,-2.51 4.86,2.51, body extent -4.86,-2.51 4.86,2.51, height 3.81
IEC_Caution_Small [mil]
  silkscreen extent -107,-93 107,92
IND_LQG15H [mm] "MuRata"
  rect 0.55x0.6 smd: 1(-0.475,0) 2(0.475,0)
  silkscreen extent -1.3,-0.3 -0.95,0.3, body extent -0.52,-0.27 0.52,0.27, height 0.55
Keystone5000 [mil] "For Keystone 500x miniature loop terminals"
  round 80 hole 40: 1(0,0)
  silkscreen extent -58,-58 58,58, body extent -49,-49 49,49, height 182
Keystone5002 [mil] "For Keystone 500x miniature loop terminals"
  round 80 hole 40: 1(0,0)
  silkscreen extent -58,-58 58,58, body extent -49,-49 49,49, height 182
Keystone5003 [mil] "For Keystone 500x miniature loop terminals"
  round 80 hole 40: 1(0,0)
  silkscreen extent -58,-58 58,58, body extent -49,-49 49,49, height 182
Keystone5004 [mil] "For Keystone 500x miniature loop terminals"
  round 80 hole 40: 1(0,0)
  silkscreen extent -58,-58 58,58, body extent -49,-49 49,49, height 182
Keystone5125 [mil] "Keystone Multipurpose loops"
  round 87 hole 63: 1(0,0)
  silkscreen extent -70,-70 70,70, body extent -63,-63 63,62, height 319
Keystone5126 [mil] "Keystone Multipurpose loops"
  round 87 hole 63: 1(0,0)
  silkscreen extent -70,-70 70,70, body extent -63,-63 63,62, height 319
Keystone5128 [mil] "Keystone Multipurpose loops"
  round 87 hole 63: 1(0,0)
  silkscreen extent -70,-70 70,70, body extent -63,-63 63,62, height 319
Keystone5129 [mil] "Keystone Multipurpose loops"
  round 87 hole 63: 1(0,0)
  silkscreen extent -70,-70 70,70, body extent -63,-63 63,62, height 319
Keystone_1902C [mil] "Hex Standoff, 4-40 threaded, nylon"
  body extent -145,-126 146,126, height 501
"LG L29K_GREEN" [mm] "OSRAM"
  rect 0.8x0.8 smd paste-0.4: 1(-0.75,0) 2(0.75,0)
  silkscreen extent -0.1,-0.5 1.45,0.5, body extent -0.9,-0.45 0.9,0.45, height 0.67
LQP_0402 [mm] "SMD, 2-Leads, Body 1.1x0.6mm"
  rect 0.55x0.6 smd: 1(-0.475,0) 2(0.475,0)
  body extent -0.55,-0.3 0.55,0.3, height 0.45
MOB0063A [mm]
  rrect12% 0.81x0.81 smd: 1(-8.05,9.525) 2(-8.05,8.255) 3(-8.05,6.985) 4(-8.05,5.715) 5(-8.05,4.445) 6(-8.05,3.175) 7(-8.05,1.905) 8(-8.05,0.635) 9(-8.05,-0.635) 10(-8.05,-1.905) 11(-8.05,-3.175) 12(-8.05,-4.445) 13(-8.05,-5.715) 14(-8.05,-6.985) 15(-8.05,-8.255) 16(-8.05,-9.525) 17(-6.35,-9.55) 18(-5.08,-9.55) 19(-3.81,-9.55) 20(-2.54,-9.55) 21(-1.27,-9.55) 22(0,-9.55) 23(1.27,-9.55) 24(2.54,-9.55) 25(3.81,-9.55) 26(5.08,-9.55) 27(6.35,-9.55) 28(8.05,-9.525) 29(8.05,-8.255) 30(8.05,-6.985) 31(8.05,-5.715) 32(8.05,-4.445) 33(8.05,-3.175) 34(8.05,-1.905) 35(8.05,-0.635) 36(8.05,0.635) 37(8.05,1.905) 38(8.05,3.175) 39(8.05,4.445) 40(8.05,5.715) 41(8.05,6.985) 42(8.05,8.255) 43(8.05,9.525) 44(6.35,9.55) 45(5.08,9.55) 46(3.81,9.55) 47(2.54,9.55) 48(1.27,9.55) 49(0,9.55) 50(-1.27,9.55) 51(-2.54,9.55) 52(-3.81,9.55) 53(-5.08,9.55) 54(-6.35,9.55)
  rrect5% 2x2 smd paste-1: 55(-4.5,4.5) 56(-4.5,1.5) 57(-4.5,-1.5) 58(-1.5,4.5) 59(-1.5,1.5) 60(-1.5,-1.5) 61(1.5,4.5) 62(1.5,1.5) 63(1.5,-1.5)
  silkscreen extent -8.97,-10.48 8.98,10.48, body extent -8.87,-10.37 8.87,10.37, height 2.46
MuRata_MM8030-2610 [mm] "Coaxial Connectors with Switch, SMD"
  rect 0.4x0.5 smd paste-0.5: 1(-0.95,0) 2(0.95,0)
  rect 0.2x0.2 smd paste-0.2: 3(0,0.75) 4(0,-0.75)
  Top Layer region: -0.32,0.45 -0.55,0.68 -0.55,1.15 0.55,1.15 0.55,0.68 0.32,0.45
  Top Layer region: -0.32,-0.45 -0.55,-0.68 -0.55,-1.15 0.55,-1.15 0.55,-0.68 0.32,-0.45
  silkscreen extent -1.3,-1.25 1.3,1.25, body extent -1.15,-1.1 1.15,1.1, height 1
"NY PMS 440 0025 PH" [mm] "4-40 nylon screw and mounting hole"
  round 8 hole 3.2: 1(0,0)
  body extent -3.3,-3.3 3.3,3.3, height 2.69
Pb-Free_Overlay_Small [mil]
  silkscreen extent -46,-46 46,46
PBC03SAAN [mm] "Sullins 100mil, 1x3, 230 mil above insulator"
  rect 1.65x1.65 hole 1.016: 1(-2.54,0)
  round 1.65 hole 1.016: 2(0,0) 3(2.54,0)
  silkscreen extent -3.81,-1.27 3.81,1.27, body extent -3.81,-1.27 3.81,1.27, height 8.38
Phoenix_1725669 [mm] "Terminal Block, 3x1, 2.54 mm, TH"
  rect 1.6x1.6 hole 1.1: 1(-2.54,0)
  round 1.6 hole 1.1: 2(0,0) 3(2.54,0)
  round 1.1 hole 1.1 unplated mask+0: 4(-2.54,-2.54) 5(0,-2.54) 6(2.54,-2.54)
  silkscreen extent -4.4,-3.1 4.04,3.1, body extent -4.04,-3.1 4.04,3.1, height 8.5
PhoenixConact_1727010 [mm]
  rect 1.7x1.7 hole 1.1: 1(-1.905,0)
  round 1.7 hole 1.1: 2(1.905,0)
  silkscreen extent -4.8,-3.6 3.81,3.6, body extent -3.81,-3.6 3.81,3.7, height 8.52
powerDI123 [mm] "Diodes Inc recommended land pattern, document number DS30628 Rev. 6-2"
  rect 2.2x1.4 smd: 1(-1.275,0)
  rect 0.9x1.4 smd: 2(1.275,0)
  silkscreen extent -3.1,-1.09 1.76,1.09, body extent -2.38,-0.97 1.52,0.96, height 1
SM_RADIAL_J16 [mm] "16 x 16.5mm:  Panasonic J16"
  rect 6.5x2.5 smd: 1(-6.25,0) 2(6.25,0)
  silkscreen extent -8.6,-8.6 8.6,8.6, body extent -8.6,-8.6 8.6,8.6, height 17
SMA [mm] "Molded Diode, 2-Leads, Body 4.3x2.6mm, IPC Medium Density, based on OnSemi component dimensions and land pattern"
  rect 2x2 smd: 1(-2,0) 2(2,0)
  silkscreen extent -3.66,-1.57 2.79,1.57, body extent -2.6,-1.3 2.6,1.3, height 2.42
SOT-23 [mm] "SOT23, 3-Leads, Body 2.9x1.3mm, Pitch 0.95mm, Lead Span 2.5mm, IPC Medium Density"
  rrect50% 1x0.6 smd: 1(-1.2,0.95) 2(-1.2,-0.95) 3(1.2,0)
  silkscreen extent -1.63,-1.5 0.7,1.5, body extent -1.16,-1.45 1.21,1.45, height 1
Sullins_PBC02SAAN [mm] "Sullins 100mil, 1x2, 230 mil above insulator"
  rect 1.65x1.65 hole 1.016: 1(0,1.27)
  round 1.65 hole 1.016: 2(0,-1.27)
  silkscreen extent -1.37,-2.54 1.27,3.1, body extent -1.27,-2.54 1.27,2.54, height 8.38
SW_B3U-1000P [mm] "OMRON"
  rect 0.8x1.7 smd: 1(-1.7,0) 2(1.7,0)
  silkscreen extent -1.5,-1.25 1.5,1.25, body extent -1.5,-1.25 1.5,1.25, height 1.75
TAYO_AH316M [mm] "SMD, 2-Leads, Body 3.2x1.6mm"
  rect 1x1.2 smd: 1(-1.6,0) 2(1.6,0)
  silkscreen extent -2.73,-0.87 0.9,0.87, body extent -1.68,-0.87 1.68,0.87, height 0.61
TDK_DEA202450BT-1294C1-H [mm] "SMD, 4-Leads, Body 2x1.25mm"
  rect 0.35x0.35 smd: 1(0,0.325) 3(0,-0.325)
  rect 0.45x1 smd: 2(0.65,0) 4(-0.65,0)
  silkscreen extent -1.17,-0.8 1.17,1.32, body extent -1.07,-0.67 1.07,0.67, height 0.8
TE_5-1814832-1 [mm] "SMA Straight PCB Socket Die Cast, TH"
  round 2 hole 1.5: 1(0,0)
  round 2.1 hole 1.6: 2(-2.54,2.54) 3(-2.54,-2.54) 4(2.54,-2.54) 5(2.54,2.54)
  silkscreen extent -1.25,-3.2 3.2,3.2, body extent -3.2,-3.2 3.2,3.2, height 9.5
TI_Stacked_Overlay_Small [mil]
  silkscreen extent -418,-98 418,98
WE-PD-S [mm] "Wurth Elektronik recommended land pattern, 2006-01-10"
  rect 2x1.7 smd: 1(-3,0) 2(3,0)
  silkscreen extent -4.3,-4 4.3,4, body extent -3.81,-3.84 3.81,3.79, height 3.5
Wurth_750315547_48 [mm] "SMD, 8-Leads, Body 9.14x9.78mm, Pitch 2.49mm"
  rect 1.17x1.91 smd: 1(-3.735,4.065) 2(-1.245,4.065) 3(1.245,4.065) 4(3.735,4.065) 5(3.735,-4.065) 6(1.245,-4.065) 7(-1.245,-4.065) 8(-3.735,-4.065)
  silkscreen extent -4.89,-3.5 4.89,3.5, body extent -4.89,-4.57 4.89,4.57, height 10.54

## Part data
C1: "CAP, CERM, 1000 pF, 100 V, +/- 10%, X7R, 0603"
C2: "CAP, AL, 330 µF, 80 V, +/- 20%, 0.17 ohm, SMD"
C3 C4: "CAP, CERM, 2.2 µF, 100 V, +/- 10%, X7R, 1210"
C5 C12 C13: "CAP, CERM, 0.1 µF, 100 V, +/- 10%, X7R, 0805"
C6: "CAP, CERM, 1000 pF, 3150 V, +80/-20%, E, Radial Disc D7x6mm"
C7: "CAP, CERM, 4.7 µF, 16 V, +/- 10%, X7R, 1206"
C8: "CAP, CERM, 0.022 µF, 100 V, +/- 10%, X7R, 0805"
C9: "CAP, CERM, 4700 pF, 100 V, +/- 10%, X7R, 0603"
C10 C11: "CAP, CERM, 100 µF, 10 V, +/- 20%, X5R, 1210"
C14: "CAP, CERM, 0.082 µF, 100 V, +/- 10%, X7R, 0805"
C15: "CAP, CERM, 1 µF, 10 V, +/- 10%, X7R, 0603"
C16 C20 C22 C23 C24 C25: "CAP, CERM, 0.1 µF, 10 V, +/- 10%, X7R, 0402"
C17: "CAP, CERM, 10 pF, 50 V, +/- 5%, C0G/NP0, 0402"
C18: "CAP, CERM, 1 pF, 50 V, +/- 10%, C0G/NP0, 0402"
C19 C21: "CAP, CERM, 4.7 µF, 6.3 V, +/- 20%, X5R, 0402"
D1: "Diode, TVS, Bi, 51 V, 400 W, SMA"
D2: "Diode, Schottky, 200 V, 1 A, PowerDI123"
D3: "Diode, Schottky, 100 V, 1 A, SMA"
D4 D6 D7: "ESD in 0402 Package with 10 pF Capacitance and 6 V Breakdown, 1 Channel, -40 to +125 degC, 2-pin X2SON (DPY), Green (RoHS & no Sb/Br)"
D5: "LED, Green, SMD"
D8 D9: "Asymmetrical TVS Diode for Extended Common-Mode RS-485, SOT-23"
E1: "ANT BLUETOOTH W-LAN ZIGBEE WIMAX, SMD"
F1: "Fuse, 2 A, 125 V, SMD"
FID1 FID2 FID3: "Fiducial mark.  There is nothing to buy or mount."
FL1: "Multilayer Chip Band Pass Filter For 2.4GHz W-LAN/Bluetooth, SMD"
H1 H2 H3 H4: "Machine Screw, Round, #4-40 x 1/4, Nylon, Philips panhead"
H5 H6 H7 H8: "Standoff, Hex, 0.5\"L #4-40 Nylon"
J1: "Conn Term Block, 2POS, 3.81mm, TH"
J2: "SMA Straight PCB Socket Die Cast, 50 Ohm, TH"
J3: "Header, 100mil, 7x2, Tin, TH"
J4: "Coaxial Connectors with Switch, 50 Ohm, SMD"
J5: "Header, 100mil, 3x1, Gold, TH"
J6 J7 J9: "Header, 100mil, 2x1, Gold, TH"
J8 J10: "Terminal Block, 3x1, 2.54 mm, TH"
L1: "Coupled inductor, 2.5 A, 0.034 ohm, SMD"
L2: "Inductor, Shielded Drum Core, Ferrite, 47 µH, 0.85 A, 0.315 ohm, SMD"
L3: "Inductor, Multilayer, Air Core, 3.6 nH, 0.3 A, 0.18 ohm, SMD"
L4: "Inductor, Film, 3.6 nH, 0.17 A, 0.5 ohm, SMD"
Logo1: library part TI_Logo, "Texas Instrument Corporate Signature"
Logo2: library part Pb-Free
Logo3: library part IEC_Caution, "IEC 61010-1 Caution Warning"
Logo4: library part FCC_disclaimer, "FCC_disclaimer"
R1 R4: "RES, 0, 5%, 0.75 W, 2010"
R2: "RES, 2.00 k, 1%, 0.063 W, 0402"
R3: "RES, 110 k, 1%, 0.063 W, 0402"
R5: "RES, 127 k, 1%, 0.063 W, 0402"
R6 R16 R17 R19 R22 R23: "RES, 100 k, 1%, 0.063 W, 0402"
R7: "RES, 17.8 k, 1%, 0.063 W, 0402"
R8: "RES, 1.96 k, 1%, 0.063 W, 0402"
R9: "RES, 3.01 k, 1%, 0.063 W, 0402"
R10 R27 R31: "RES, 0, 5%, 0.1 W, 0603"
R12 R13 R14 R15: "RES, 0, 5%, 0.063 W, 0402"
R18 R24: "RES, 2.67 k, 1%, 0.063 W, 0402"
R20: "RES, 270, 5%, 0.063 W, 0402"
R21: "RES, 402, 1%, 0.063 W, 0402"
R25 R35 R36 R37: "RES, 10.0, 1%, 0.063 W, 0402"
R28 R30 R32 R34: "RES, 348, 1%, 0.1 W, 0603"
R29 R33: "RES, 120, 1%, 0.1 W, 0603"
S1: "SWITCH TACTILE SPST-NO 0.05A 12V"
T1: "Transformer, 42 uH, SMT"
TP1 TP4: "Test Point, Miniature, White, TH"
TP2 TP3: "Test Point, Miniature, Red, TH"
TP5 TP6: "Test Point, Multipurpose, Grey, TH"
TP7 TP9: "Test Point, Miniature, Orange, TH"
TP8 TP10: "Test Point, Miniature, Yellow, TH"
TP11: "Test Point, Multipurpose, Green, TH"
TP12: "Test Point, Multipurpose, Purple, TH"
TP13: "Test Point, Multipurpose, Brown, TH"
U1: "Wide Input 65V, 1.5A Synchronous Step-Down DC-DC Converter, DNT0012B"
U2: "Capacitor-Free, 150-mA, Low-Dropout Regulator with Foldback Current Limit for Portable Devices, DBV0005A"
U3: "SimpleLink™ Wi-Fi ® and Internet-of-Things Module Solution, a Single-Chip Wireless MCU, MOB0063A"
U4: "Isolated 3.3 V RS-485 Transceiver, 1 Mbps, 3.3 V, Half Duplex, -40 to 85 degC, 16-pin SOIC (DW), Green (RoHS & no Sb/Br)"
U5: "3.3V-Supply RS-485 with IEC ESD Protection, D0008A"
ZZ1 ZZ2 ZZ3 ZZ4: library part AssemblyNote

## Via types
v1: diameter 22, hole 10, Top Layer to Bottom Layer, tented both sides, 276 vias
v2: diameter 18, hole 8, Top Layer to Bottom Layer, tented both sides, 233 vias
v3: diameter 19.68, hole 7.87, Top Layer to Bottom Layer, 41 vias
v4: diameter 22, hole 10, Top Layer to Bottom Layer, 1 vias

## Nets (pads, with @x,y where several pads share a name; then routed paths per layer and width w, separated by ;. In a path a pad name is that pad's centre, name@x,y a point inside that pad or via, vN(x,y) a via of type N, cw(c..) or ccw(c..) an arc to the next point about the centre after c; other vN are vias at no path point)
3V3: C19.1 C20.1 C21.1 D5.1 R4.2 R14.2 R16.2 R17.2 R19.2 R20.2 R27.2 R31.2 R32.2 U3.36 U3.37 U3.40 | length 2032
  Top Layer w10: v1(2200,2240) 2200,2263.62 R17.2@2201.38,2265 ; v1(2200,2390) 2201.38,2388.62 R16.2@2201.38,2365 ; v1(2485,845) 2485,878.5 R32.2@2486.5,880 ; 2746.38,2651.38 R19.2@2746.38,2750 ; R14.2@2975,1191.38 2976.38,1190 v1(3000,1190) ; v1(3130,1190) 3159.53,1190 D5.1@3160,1189.53 ; v1(3375,1990) 3375,2017.49 R20.2@3375.92,2018.41
  Signal Layer 2 w10: v1(2300,590) 2310,600 2310,720 2435,845 v1(2485,845) ; v1@2809,1125 2814,1130 2940,1130 v1(3000,1190) v1(3130,1190) 3290,1190 3445,1345 3445,1580 3375,1650 v1(3375,1990)
  other v1: 2300,565 2785,1130 2810,1130 2015,2195 2055,2195 2015,2220 2055,2220 2055,2245 2520,2625 2725,2625 2550,2650 2725,2650 2725,2675 2695,2705 2720,2705
3V3_ISO: C15.1 C24.2 R28.2 TP13.1 U2.5 U4.16 | length 955
  Top Layer w10: R28.2@1085,786.5 1118.5,786.5 v1(1120,785) ; C24.2@1619,521.38 C24.2@1620.38,520
  Top Layer w20: C24.2@1620.38,520 U4.16@1729.87,520
  Signal Layer 2 w10: v1(1120,785) 1165,830 v1(1635,830) ; TP13.1@1360,395 1470,395 1565,490 v1(1565,520)
  other v1: 1590,520 1625,855
3V3_OUT: C9.1 C10.1 C11.1 L2.2 R4.1 R8.2 T1.3 T1.4 TP3.1 | length 1062.1
  Top Layer w10: v1@1033.5,1930.5 1034,1930.01 v1(1034,1927) ; v1@1033.5,2008.5 1035,2010 1036.38,2011.38 R8.2@1036.38,2040
  Top Layer w15: v1@1033.5,1930.5 C9.1@1033.5,1960
  Signal Layer 2 w10: v1(1037,2011) 1579,2011 v1(1580,2010)
  Signal Layer 2 w15: v1(1034,1927) 1484,1927 v1(1486,1929)
485_NRE/DE: R18.2 U3.50 U4.4 U4.5 U5.2 U5.3 | length 2018.2
  Top Layer w10: U4.4@2088.13,670 2150,670 2165,685 2165,720 ; U4.5@2088.13,720 2165,720 ; v1(2360,2165) 2360.97,2164.03 U3.50@2392.94,2164.03 ; v1(2381.38,1781.38) R18.2@2381.38,1754 2381.38,1678.62 2490,1570 2490,1440 2605,1325 U5.2@2605,1210 ; U5.2@2606,1200.49 U5.3@2556,1200.49 2556,1146 2545,1135 2475,1135 2255,915 2255,810 2165,720
  Signal Layer 2 w10: v1(2360,2165) 2360,1880 2381.38,1858.62 v1(2381.38,1781.38)
485_RX: TP10.1 U3.49 U4.3 U5.1 | length 2173.6
  Top Layer w10: U4.3@2088.13,620 2150,620 2300,770 2300,905 2505,1110 2635,1110 2656,1131 U5.1@2656,1200.49 2656,1354 2572,1438 TP10.1@2572,1496 2572,1698 2450,1820 2370,1820 2325,1865 2325,2180 2359.03,2214.03 U3.49@2392.94,2214.03
485_TX: R17.1 TP9.1 U3.48 U4.6 U5.4 | length 1973.5
  Top Layer w10: U4.6@2088.13,770 2155,770 2210,825 2210,930 2480.49,1200.49 U5.4@2506,1200.49 2506,1353 TP9.1@2366,1493 2248.62,1610.38 R17.1@2248.62,2265 2391.97,2265 U3.48@2392.94,2264.03
ANT_LEG: J4.1 R15.1 | length 69.9
  Top Layer w18: R15.1@2994,2767.69 J4.1@2994,2837.6
BST: C8.2 U1.10 | length 105.2
  Top Layer w10: C8.2@1289,2040 1295,2040 1328.84,2073.84 1328.84,2080.08 1328.87,2099.89 U1.10@1328.84,2125.2
CC_RF_OUT: FL1.1 U3.31 | length 96.2
  Top Layer w18: U3.31@2993.92,2530.96 FL1.1@2993.92,2627.13
FB: C13.2 R8.1 R9.2 U1.8 | length 300.4
  Top Layer w10: R9.2@1083.62,2090 R8.1@1083.62,2040 1181,2040 1231,2090 1270,2090 1289.47,2109.47 U1.8@1289.47,2125.2
FLASH_RX: D7.1 J5.2 R16.1 TP7.1 U3.46 | length 925.3
  Top Layer w10: J5.2@2120,3092 2120.32,3091.69 D7.1@2120.32,2970 2120.32,2835.69 TP7.1@2249,2707 2248.62,2706.62 R16.1@2248.62,2365 2249.59,2364.03 U3.46@2392.94,2364.03
FLASH_TX: D6.1 J5.1 TP8.1 U3.47 | length 1080.7
  Top Layer w10: J5.1@2020,3092 2019.68,3091.69 D6.1@2019.68,2970 2019.68,2839.69 1998,2818 TP8.1@1998,2708 1998,2487 2170.97,2314.03 U3.47@2392.94,2314.03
